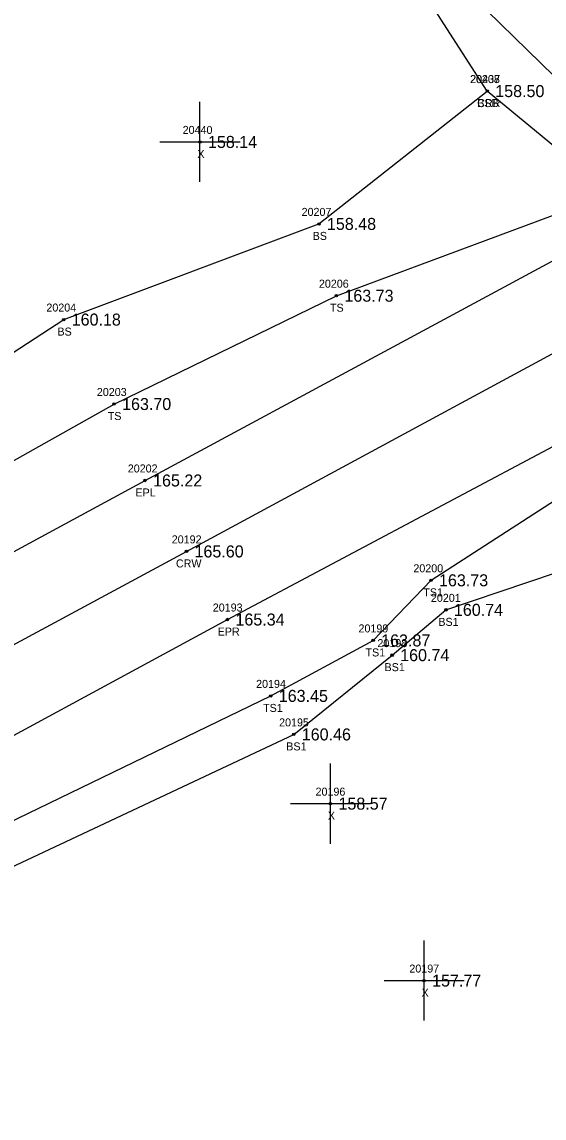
# Model space of a CAD drawing. Extents: x 2279528 to 2280976, y 1061373 to 1062235.
# Drawn here: x 2280127.5 to 2280192.7, y 1061681.1 to 1061818 of the extents above; entities that cross this region are included whole.
import ezdxf

# ---------------------------------------------------------------- set-up
doc = ezdxf.new("R2010")
doc.units = 0
for name, color, linetype in [('RD_DTM_BkLn1', 7, 'Continuous'), ('RD_DTM_BkLn2', 7, 'Continuous'), ('RD_DTM_BkLn_txCode', 7, 'Continuous'), ('RD_EX_H2O', 7, 'Continuous'), ('RD_EX_H2O_txCode', 7, 'Continuous'), ('RD_EX_Misc', 7, 'Continuous'), ('RD_EX_Misc_txCode', 7, 'Continuous'), ('RD_EX_Road', 7, 'Continuous'), ('RD_EX_Road_txCode', 7, 'Continuous'), ('RD_EX_TX_H2O_ELEV', 7, 'Continuous'), ('RD_EX_TX_Misc_ELEV', 7, 'Continuous'), ('RD_EX_TX_Road_ELEV', 7, 'Continuous'), ('RD_HC_Survey_ELEV', 7, 'Continuous'), ('RD_HC_Survey_txCode', 7, 'Continuous'), ('RD_SMD_Locator', 7, 'Continuous')]:
    doc.layers.add(name, color=color, linetype=linetype)

msp = doc.modelspace()

# ---------------------------------------------------------------- linework, layer by layer
at = {"layer": 'RD_DTM_BkLn1'}
msp.add_lwpolyline([(2279559.79, 1061433.13), (2279641.23, 1061477.49), (2279727.93, 1061524.84), (2279814.76, 1061571.75), (2279901.26, 1061618.64), (2279982.8, 1061662.56), (2280064.7, 1061706.86), (2280148.08, 1061751.86), (2280234.22, 1061798.46), (2280310.96, 1061840.01), (2280397.69, 1061887.57), (2280487.27, 1061936.5), (2280573.03, 1061983.12), (2280654.64, 1062027.66), (2280741.28, 1062074.45), (2280833.39, 1062123.87), (2280892.52, 1062155.9), (2280939.46, 1062181.85)], dxfattribs=at)
at = {"layer": 'RD_DTM_BkLn2'}
for points in [[(2279912.54, 1061647.23), (2279971.15, 1061682.49), (2280052.17, 1061728.33), (2280132.75, 1061780.82), (2280164.61, 1061792.77), (2280185.62, 1061809.36)], [(2279918.28, 1061645.97), (2279973.97, 1061675.02), (2280055.41, 1061723.24), (2280139.04, 1061770.27), (2280166.79, 1061783.8), (2280197.35, 1061795.14), (2280211.16, 1061800.79)], [(2280059.22, 1061681.62), (2280071.78, 1061691.76), (2280158.6, 1061733.81), (2280171.38, 1061740.74), (2280178.6, 1061748.25), (2280197.42, 1061760.44), (2280219.45, 1061768.68)], [(2280066.92, 1061680.28), (2280073.37, 1061687.57), (2280161.47, 1061729), (2280173.75, 1061738.9), (2280180.46, 1061744.56), (2280207.84, 1061753.79), (2280214.1, 1061757.73), (2280223.01, 1061764.94)]]:
    msp.add_lwpolyline(points, dxfattribs=at)
at = {"layer": 'RD_EX_H2O'}
for points in [[(2280211.16, 1061800.79), (2280200.18, 1061802.95), (2280195.55, 1061801.16), (2280185.62, 1061809.36), (2280166.4, 1061839.27), (2280165.19, 1061847.77), (2280176.13, 1061895.97), (2280173.38, 1061913.11), (2280146.96, 1061940.88), (2280090.97, 1061964.76), (2280049.27, 1062002.4), (2280058.65, 1062048.88), (2280050.78, 1062064.28), (2280035.9, 1062083.09), (2280001.73, 1062095.49), (2279975.65, 1062129.45), (2279976.82, 1062173.44)], [(2280211.72, 1061801.11), (2280200.63, 1061804.74), (2280175.61, 1061829.17), (2280168.33, 1061843.42)]]:
    msp.add_lwpolyline(points, dxfattribs=at)
at = {"layer": 'RD_EX_Misc'}
for p, q in [((2280149.76, 1061798.01), (2280149.76, 1061808.01)), ((2280144.76, 1061803.01), (2280154.76, 1061803.01)), ((2280166.05, 1061715.35), (2280166.05, 1061725.35)), ((2280161.05, 1061720.35), (2280171.05, 1061720.35)), ((2280177.74, 1061693.25), (2280177.74, 1061703.25)), ((2280172.74, 1061698.25), (2280182.74, 1061698.25))]:
    msp.add_line(p, q, dxfattribs=at)
at = {"layer": 'RD_EX_Road'}
for points in [[(2279554.31, 1061441.46), (2279636.61, 1061486.51), (2279673.46, 1061506.76), (2279683.06, 1061512.21), (2279723.14, 1061533.54), (2279809.28, 1061580.29), (2279896.91, 1061627.91), (2279977.07, 1061671.02), (2280059.64, 1061715.57), (2280142.91, 1061760.72), (2280228.83, 1061807.06), (2280306.04, 1061849.18), (2280392.98, 1061896.71), (2280482.82, 1061945.75), (2280567.83, 1061991.78), (2280649.94, 1062036.55), (2280660.56, 1062042.19), (2280676.12, 1062050.66), (2280737.28, 1062083.64), (2280828.54, 1062132.77), (2280887.86, 1062164.61), (2280934.91, 1062190.9)], [(2279906, 1061609.76), (2279987.33, 1061653.65), (2280069.09, 1061697.76), (2280153.19, 1061743.35), (2280194.51, 1061765.35), (2280202.82, 1061771.34), (2280211.47, 1061775.32), (2280215.93, 1061780.7), (2280225.22, 1061785.77), (2280231.78, 1061787.38), (2280251.88, 1061797.82), (2280255.66, 1061801.36), (2280256.83, 1061804.75), (2280266.2, 1061806.83), (2280270.78, 1061807.29), (2280284.33, 1061814.31), (2280315.09, 1061831.32), (2280403.05, 1061879.04), (2280492, 1061927.92)]]:
    msp.add_lwpolyline(points, dxfattribs=at)
at = {"layer": 'RD_SMD_Locator'}
for centre in [(2280185.62, 1061809.36), (2280185.62, 1061809.36), (2280149.76, 1061803.01), (2280164.61, 1061792.77), (2280166.79, 1061783.8), (2280132.75, 1061780.82), (2280139.04, 1061770.27), (2280142.91, 1061760.72), (2280148.08, 1061751.86), (2280178.6, 1061748.25), (2280180.46, 1061744.56), (2280153.19, 1061743.35), (2280171.38, 1061740.74), (2280173.75, 1061738.9), (2280158.6, 1061733.81), (2280161.47, 1061729), (2280166.05, 1061720.35), (2280177.74, 1061698.25)]:
    msp.add_circle(centre, 0.15, dxfattribs=at)

# ---------------------------------------------------------------- texts
at = {"layer": 'RD_DTM_BkLn_txCode'}
for s, p in [('20208', (2280183.47, 1061810.36)), ('BSB', (2280184.37, 1061807.36)), ('20207', (2280162.45, 1061793.77)), ('BS', (2280163.83, 1061790.77)), ('20206', (2280164.61, 1061784.8)), ('20204', (2280130.59, 1061781.82)), ('TS', (2280165.99, 1061781.8)), ('BS', (2280131.97, 1061778.82)), ('20203', (2280136.89, 1061771.27)), ('TS', (2280138.25, 1061768.27)), ('20200', (2280176.4, 1061749.25)), ('TS1', (2280177.64, 1061746.25)), ('20201', (2280178.59, 1061745.56)), ('BS1', (2280179.52, 1061742.56)), ('20199', (2280169.55, 1061741.74)), ('20198', (2280171.91, 1061739.9)), ('TS1', (2280170.42, 1061738.74)), ('BS1', (2280172.8, 1061736.9)), ('20194', (2280156.77, 1061734.81)), ('TS1', (2280157.64, 1061731.81)), ('20195', (2280159.64, 1061730)), ('BS1', (2280160.53, 1061727))]:
    msp.add_text(s, height=1, dxfattribs=at).set_placement(p)
at = {"layer": 'RD_EX_H2O_txCode'}
for s, p in [('20437', (2280183.5, 1061810.36)), ('CRR', (2280184.37, 1061807.36))]:
    msp.add_text(s, height=1, dxfattribs=at).set_placement(p)
at = {"layer": 'RD_EX_Misc_txCode'}
for s, p in [('20440', (2280147.6, 1061804.01)), ('X', (2280149.44, 1061801.01)), ('20196', (2280164.19, 1061721.35)), ('X', (2280165.73, 1061718.35)), ('20197', (2280175.9, 1061699.25)), ('X', (2280177.42, 1061696.25))]:
    msp.add_text(s, height=1, dxfattribs=at).set_placement(p)
at = {"layer": 'RD_EX_Road_txCode'}
for s, p in [('20202', (2280140.75, 1061761.72)), ('EPL', (2280141.71, 1061758.72)), ('20193', (2280151.36, 1061744.35)), ('EPR', (2280151.97, 1061741.35))]:
    msp.add_text(s, height=1, dxfattribs=at).set_placement(p)
at = {"layer": 'RD_EX_TX_H2O_ELEV'}
msp.add_text('158.50', height=1.5, dxfattribs=at).set_placement((2280186.62, 1061808.61))
at = {"layer": 'RD_EX_TX_Misc_ELEV'}
for s, p in [('158.50', (2280186.62, 1061808.61)), ('158.14', (2280150.76, 1061802.26)), ('158.48', (2280165.61, 1061792.02)), ('163.73', (2280167.79, 1061783.05)), ('160.18', (2280133.75, 1061780.07)), ('163.70', (2280140.04, 1061769.52)), ('163.73', (2280179.6, 1061747.5)), ('160.74', (2280181.46, 1061743.81)), ('163.87', (2280172.38, 1061739.99)), ('160.74', (2280174.75, 1061738.15)), ('163.45', (2280159.6, 1061733.06)), ('160.46', (2280162.47, 1061728.25)), ('158.57', (2280167.05, 1061719.6)), ('157.77', (2280178.74, 1061697.5))]:
    msp.add_text(s, height=1.5, dxfattribs=at).set_placement(p)
at = {"layer": 'RD_EX_TX_Road_ELEV'}
for s, p in [('165.22', (2280143.91, 1061759.97)), ('165.34', (2280154.19, 1061742.6))]:
    msp.add_text(s, height=1.5, dxfattribs=at).set_placement(p)
at = {"layer": 'RD_HC_Survey_ELEV'}
msp.add_text('165.60', height=1.5, dxfattribs=at).set_placement((2280149.08, 1061751.11))
at = {"layer": 'RD_HC_Survey_txCode'}
for s, p in [('20192', (2280146.24, 1061752.86)), ('CRW', (2280146.76, 1061749.86))]:
    msp.add_text(s, height=1, dxfattribs=at).set_placement(p)

doc.saveas('drawing.dxf')
